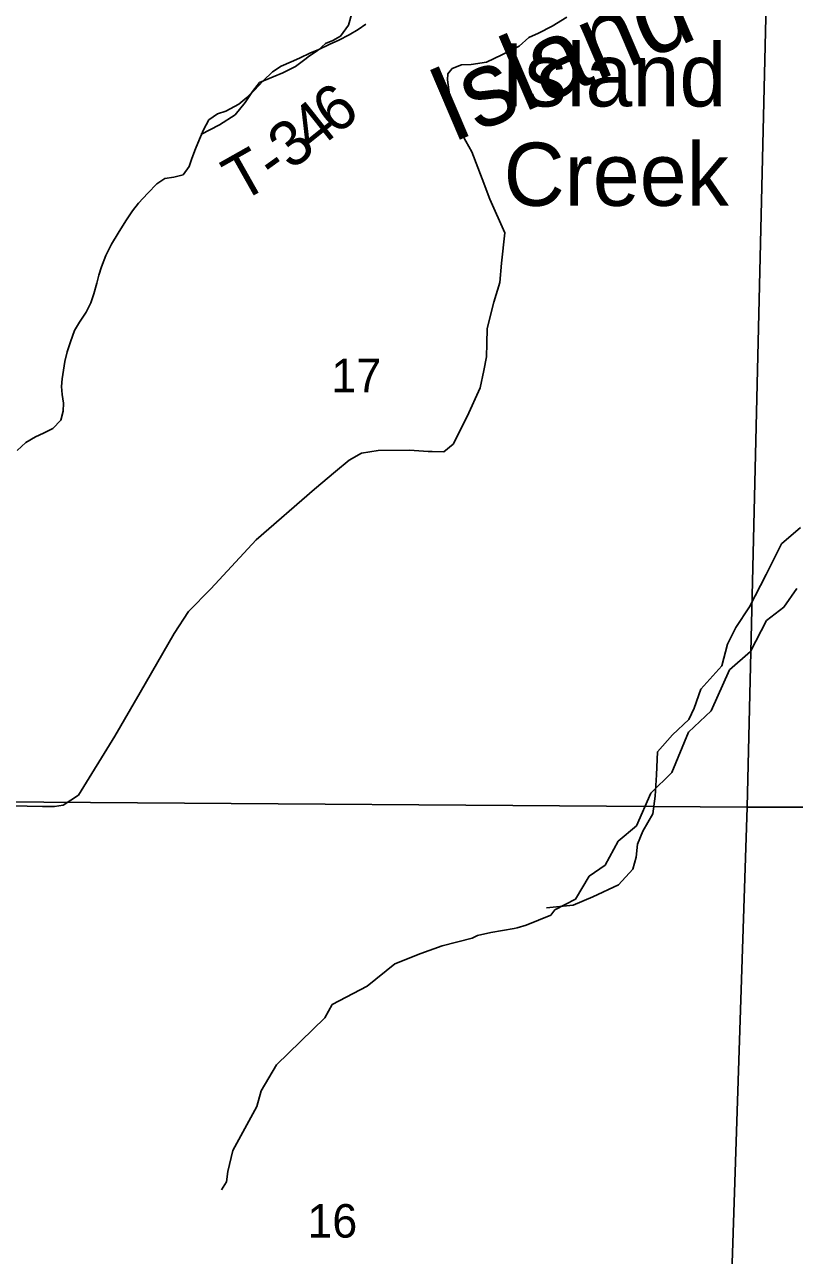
# Model space of a CAD drawing. Extents: x 0 to 34, y 0 to 22.
# Drawn here: x 3.589 to 4.552, y 16.55 to 18.088 of the extents above; entities that cross this region are included whole.
import ezdxf

# ---------------------------------------------------------------- set-up
doc = ezdxf.new("R2010")
doc.units = 0
for name, color, linetype in [('GM_X_Minor_River', 7, 'Continuous'), ('GM_X_Minor_River_Text', 7, 'Continuous'), ('GM_X_Section', 7, 'Continuous'), ('GM_X_Section_Text', 7, 'Continuous'), ('GM_X_Township_Road', 7, 'Continuous'), ('GM_X_Township_Road_Text', 7, 'Continuous'), ('GM_X_Unincorporated_Text', 7, 'Continuous')]:
    doc.layers.add(name, color=color, linetype=linetype)

msp = doc.modelspace()

# ---------------------------------------------------------------- linework, layer by layer
at = {"layer": 'GM_X_Minor_River'}
for p, q in [((4.0066, 18.0823), (3.995, 18.0755)), ((4.0162, 18.0891), (4.0066, 18.0823)), ((3.9823, 18.069), (3.9703, 18.0633)), ((3.995, 18.0755), (3.9823, 18.069)), ((3.947, 18.0531), (3.9332, 18.0465)), ((3.9572, 18.0572), (3.947, 18.0531)), ((3.9703, 18.0633), (3.9572, 18.0572)), ((3.9103, 18.0363), (3.8991, 18.0291)), ((3.9227, 18.042), (3.9103, 18.0363)), ((3.9332, 18.0465), (3.9227, 18.042)), ((3.8877, 18.0181), (3.8766, 18.0063)), ((3.8991, 18.0291), (3.8877, 18.0181)), ((3.8766, 18.0063), (3.867, 17.9973)), ((3.8574, 17.989), (3.8409, 17.9801)), ((3.867, 17.9973), (3.8574, 17.989)), ((3.8304, 17.9767), (3.8196, 17.9692)), ((3.8409, 17.9801), (3.8304, 17.9767)), ((3.8131, 17.9568), (3.8078, 17.9452)), ((3.8196, 17.9692), (3.8131, 17.9568)), ((3.8078, 17.9452), (3.8028, 17.9329)), ((3.8028, 17.9329), (3.7983, 17.9209)), ((3.7952, 17.9109), (3.7875, 17.9004)), ((3.7983, 17.9209), (3.7952, 17.9109)), ((3.7648, 17.8959), (3.7548, 17.8891)), ((3.7758, 17.8978), (3.7648, 17.8959)), ((3.7875, 17.9004), (3.7758, 17.8978)), ((3.7548, 17.8891), (3.7433, 17.8777)), ((3.7319, 17.8652), (3.7243, 17.8554)), ((3.7433, 17.8777), (3.7319, 17.8652)), ((3.7243, 17.8554), (3.7159, 17.843)), ((3.7159, 17.843), (3.7061, 17.8278)), ((3.7061, 17.8278), (3.6978, 17.8139)), ((3.6978, 17.8139), (3.691, 17.7996)), ((3.691, 17.7996), (3.6854, 17.7857)), ((3.6819, 17.7749), (3.6795, 17.765)), ((3.6854, 17.7857), (3.6819, 17.7749)), ((3.6795, 17.765), (3.6757, 17.7519)), ((3.6757, 17.7519), (3.6719, 17.7407)), ((3.6662, 17.7288), (3.6578, 17.7163)), ((3.6719, 17.7407), (3.6662, 17.7288)), ((3.6578, 17.7163), (3.6517, 17.7059)), ((3.6517, 17.7059), (3.6468, 17.6916)), ((3.6468, 17.6916), (3.6426, 17.6793)), ((3.6396, 17.667), (3.638, 17.6563)), ((3.6426, 17.6793), (3.6396, 17.667)), ((3.638, 17.6563), (3.6364, 17.6456)), ((3.6364, 17.6456), (3.6356, 17.6361)), ((3.6356, 17.6361), (3.6363, 17.6258)), ((3.6363, 17.6258), (3.6378, 17.6152)), ((3.6373, 17.6049), (3.6346, 17.5938)), ((3.6378, 17.6152), (3.6373, 17.6049)), ((3.6346, 17.5938), (3.6247, 17.5836)), ((3.6029, 17.573), (3.5906, 17.5658)), ((3.6127, 17.5775), (3.6029, 17.573)), ((3.6247, 17.5836), (3.6127, 17.5775)), ((3.5906, 17.5658), (3.5799, 17.5559)), ((4.5549, 17.3834), (4.5387, 17.36)), ((4.5387, 17.36), (4.517, 17.3432)), ((4.517, 17.3432), (4.4973, 17.3048)), ((4.4973, 17.3048), (4.4708, 17.2816)), ((4.4708, 17.2816), (4.4479, 17.2306)), ((4.4479, 17.2306), (4.4196, 17.2038)), ((4.4196, 17.2038), (4.3986, 17.1533)), ((4.3986, 17.1533), (4.3726, 17.1277)), ((4.3726, 17.1277), (4.3544, 17.0867)), ((4.3544, 17.0867), (4.3316, 17.0677)), ((4.3316, 17.0677), (4.3155, 17.0373)), ((4.3155, 17.0373), (4.2953, 17.0237)), ((4.2953, 17.0237), (4.2781, 16.9952)), ((4.2781, 16.9952), (4.2526, 16.9815)), ((4.2474, 16.9749), (4.2166, 16.9623)), ((4.2526, 16.9815), (4.2474, 16.9749)), ((4.2016, 16.9582), (4.1722, 16.9532)), ((4.2053, 16.959), (4.2016, 16.9582)), ((4.2166, 16.9623), (4.2053, 16.959)), ((4.1492, 16.9463), (4.1116, 16.9366)), ((4.1556, 16.9495), (4.1492, 16.9463)), ((4.1722, 16.9532), (4.1556, 16.9495)), ((4.0849, 16.927), (4.0523, 16.9143)), ((4.1116, 16.9366), (4.0849, 16.927)), ((4.0523, 16.9143), (4.0176, 16.8863)), ((4.0176, 16.8863), (3.9738, 16.8635)), ((3.9738, 16.8635), (3.9646, 16.8466)), ((3.9646, 16.8466), (3.9044, 16.7878)), ((3.9044, 16.7878), (3.8853, 16.7555)), ((3.8853, 16.7555), (3.8799, 16.7356)), ((3.8799, 16.7356), (3.8499, 16.6807)), ((3.8499, 16.6807), (3.8435, 16.6547)), ((3.8435, 16.6547), (3.8419, 16.6418)), ((3.8419, 16.6418), (3.8356, 16.6318))]:
    msp.add_line(p, q, dxfattribs=at)
at = {"layer": 'GM_X_Section'}
for p, q in [((4.5166, 18.1148), (4.4928, 17.1099)), ((4.4928, 17.1099), (4.5166, 18.1148)), ((4.4928, 17.1099), (3.4934, 17.1171)), ((3.4934, 17.1171), (4.4928, 17.1099)), ((5.492, 17.1117), (4.4928, 17.1099)), ((4.4928, 17.1099), (5.492, 17.1117)), ((4.4928, 17.1099), (4.4591, 16.088)), ((4.4591, 16.088), (4.4928, 17.1099))]:
    msp.add_line(p, q, dxfattribs=at)
at = {"layer": 'GM_X_Township_Road'}
for p, q in [((3.9943, 18.0877), (4.0121, 18.1516)), ((4.249, 18.0865), (4.2675, 18.0977)), ((3.9844, 18.074), (3.9943, 18.0877)), ((4.232, 18.0778), (4.249, 18.0865)), ((3.9564, 18.0564), (3.9655, 18.0648)), ((3.9655, 18.0648), (3.9748, 18.0686)), ((3.9748, 18.0686), (3.9844, 18.074)), ((4.2078, 18.0613), (4.2198, 18.0723)), ((4.2198, 18.0723), (4.232, 18.0778)), ((3.9399, 18.0447), (3.9457, 18.0491)), ((3.9457, 18.0491), (3.9564, 18.0564)), ((4.167, 18.0412), (4.1861, 18.0504)), ((4.1861, 18.0504), (4.2078, 18.0613)), ((3.9122, 18.0282), (3.9282, 18.0361)), ((3.9282, 18.0361), (3.9382, 18.0435)), ((3.9382, 18.0435), (3.9399, 18.0447)), ((4.1185, 18.0269), (4.1241, 18.0333)), ((4.1241, 18.0333), (4.1355, 18.038)), ((4.1355, 18.038), (4.1479, 18.0386)), ((4.1479, 18.0386), (4.167, 18.0412)), ((3.8829, 18.0159), (3.9, 18.0231)), ((3.9, 18.0231), (3.9122, 18.0282)), ((4.1181, 18.0195), (4.1185, 18.0269)), ((4.12, 18.0067), (4.1181, 18.0195)), ((3.8651, 17.9911), (3.8743, 18.0049)), ((3.8743, 18.0049), (3.8829, 18.0159)), ((4.1232, 17.9868), (4.12, 18.0067)), ((3.8525, 17.9754), (3.8651, 17.9911)), ((3.833, 17.9631), (3.8525, 17.9754)), ((4.1338, 17.9561), (4.1232, 17.9868)), ((3.8097, 17.9511), (3.833, 17.9631)), ((4.1487, 17.9291), (4.1338, 17.9561)), ((4.1615, 17.8955), (4.1487, 17.9291)), ((4.1713, 17.87), (4.1615, 17.8955)), ((4.1898, 17.828), (4.1713, 17.87)), ((4.1859, 17.7899), (4.1898, 17.828)), ((4.1835, 17.766), (4.1859, 17.7899)), ((4.176, 17.7412), (4.1835, 17.766)), ((4.1678, 17.7086), (4.176, 17.7412)), ((4.1675, 17.6895), (4.1678, 17.7086)), ((4.1668, 17.673), (4.1675, 17.6895)), ((4.1636, 17.6561), (4.1668, 17.673)), ((4.159, 17.6343), (4.1636, 17.6561)), ((4.1427, 17.5984), (4.159, 17.6343)), ((4.1252, 17.5639), (4.1427, 17.5984)), ((4.0313, 17.5558), (4.0706, 17.5564)), ((4.0706, 17.5564), (4.0942, 17.5547)), ((4.1137, 17.5544), (4.1252, 17.5639)), ((3.9781, 17.5298), (3.9953, 17.544)), ((3.9953, 17.544), (4.0106, 17.5526)), ((4.0106, 17.5526), (4.0313, 17.5558)), ((4.0942, 17.5547), (4.099, 17.5547)), ((4.099, 17.5547), (4.1137, 17.5544)), ((3.9517, 17.5074), (3.9781, 17.5298)), ((3.8789, 17.4441), (3.9517, 17.5074)), ((4.5595, 17.4596), (4.536, 17.4394)), ((3.8222, 17.383), (3.8789, 17.4441)), ((4.536, 17.4394), (4.5166, 17.4007)), ((4.5166, 17.4007), (4.4957, 17.3604)), ((3.7944, 17.3548), (3.8222, 17.383)), ((4.4957, 17.3604), (4.4788, 17.3347)), ((3.7763, 17.3273), (3.7944, 17.3548)), ((3.7337, 17.2533), (3.7763, 17.3273)), ((4.4788, 17.3347), (4.4682, 17.3136)), ((4.4682, 17.3136), (4.4611, 17.2865)), ((4.4611, 17.2865), (4.4351, 17.2575)), ((3.7021, 17.1987), (3.7337, 17.2533)), ((4.4351, 17.2575), (4.4268, 17.2338)), ((4.4268, 17.2338), (4.4199, 17.2197)), ((4.4199, 17.2197), (4.3994, 17.2003)), ((3.6567, 17.1251), (3.7021, 17.1987)), ((4.3994, 17.2003), (4.3809, 17.1791)), ((4.3809, 17.1791), (4.3795, 17.1506)), ((4.3795, 17.1506), (4.3777, 17.1239)), ((3.5133, 17.1127), (3.6117, 17.111)), ((3.6117, 17.111), (3.6266, 17.1107)), ((3.6266, 17.1107), (3.6375, 17.1124)), ((3.6375, 17.1124), (3.6567, 17.1251)), ((4.3777, 17.1239), (4.375, 17.1015)), ((4.375, 17.1015), (4.3625, 17.08)), ((4.3625, 17.08), (4.3556, 17.0639)), ((4.3556, 17.0639), (4.354, 17.0475)), ((4.354, 17.0475), (4.3501, 17.0323)), ((4.3501, 17.0323), (4.3319, 17.0129)), ((4.3319, 17.0129), (4.3, 16.9979)), ((4.2752, 16.9876), (4.242, 16.984)), ((4.3, 16.9979), (4.2752, 16.9876))]:
    msp.add_line(p, q, dxfattribs=at)

# ---------------------------------------------------------------- texts
at = {"layer": 'GM_X_Minor_River_Text'}
msp.add_text('Island', height=0.09472, rotation=23.1154, dxfattribs=at).set_placement((4.1229, 17.9398))
at = {"layer": 'GM_X_Section_Text'}
for s, p in [('17', (3.973, 17.6287)), ('16', (3.943, 16.5719))]:
    msp.add_text(s, height=0.04186, rotation=0, dxfattribs=at).set_placement(p)
at = {"layer": 'GM_X_Township_Road_Text'}
for s, rotation, p in [('6', 37.3788, (3.9773, 17.9488)), ('4', 38.6208, (3.9503, 17.9271)), ('3', 38.6367, (3.9229, 17.9053)), ('T', 29.418, (3.8587, 17.8651)), ('-', 35.8589, (3.9016, 17.8898))]:
    msp.add_text(s, height=0.0568, rotation=rotation, dxfattribs=at).set_placement(p)
at = {"layer": 'GM_X_Unincorporated_Text'}
for s, p in [('Island', (4.1851, 17.986)), ('Creek', (4.1884, 17.8618))]:
    msp.add_text(s, height=0.07898, rotation=0, dxfattribs=at).set_placement(p)

doc.saveas('drawing.dxf')
